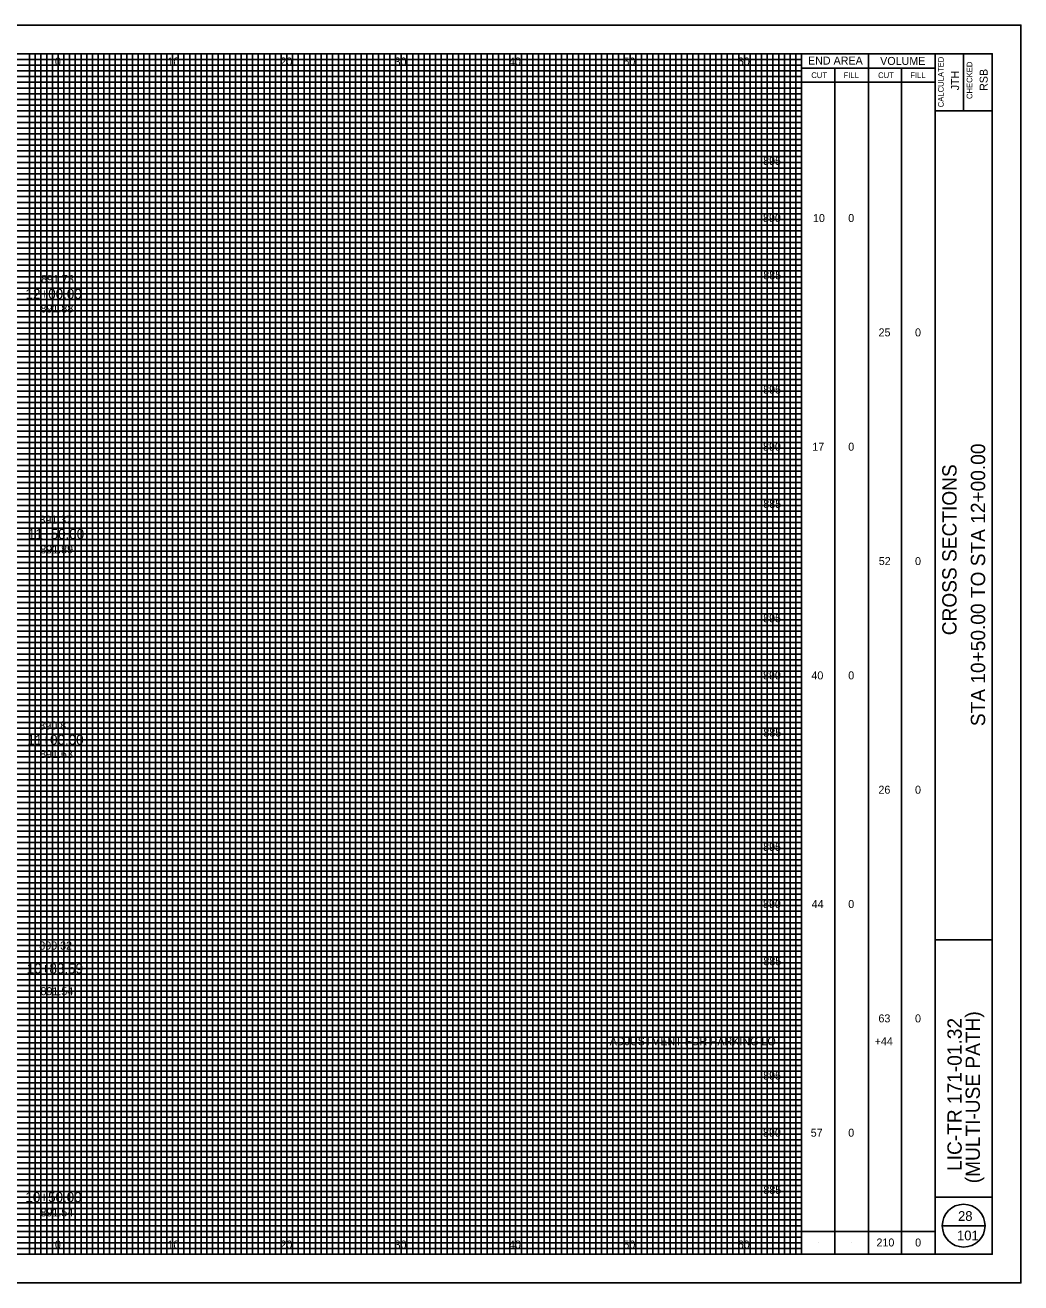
# Model space of a CAD drawing. Extents: x -10 to 160, y -2 to 2522.
# Drawn here: x 72.9 to 160, y -2.5 to 107.5 of the extents above; entities that cross this region are included whole.
import ezdxf

# ---------------------------------------------------------------- set-up
doc = ezdxf.new("R2010")
doc.units = 0
for name, color, linetype in [('GK_Cells', 7, 'Continuous'), ('GK_Patterns', 7, 'Continuous'), ('TX_P_10', 7, 'Continuous'), ('TX_X_10', 7, 'Continuous'), ('XS_P_Finished_Grade_Seeded', 7, 'Continuous'), ('XS_P_Pavt_Surface', 7, 'Continuous'), ('XS_P_Subgrade', 7, 'Continuous'), ('XS_X_Ground_Line', 7, 'Continuous')]:
    doc.layers.add(name, color=color, linetype=linetype)

msp = doc.modelspace()

# ---------------------------------------------------------------- linework, layer by layer
at = {"layer": 'GK_Cells'}
msp.add_lwpolyline([(-10, -2.5), (160, -2.5), (160, 107.5), (-10, 107.5)], close=True, dxfattribs=at)
at = {"layer": 'TX_P_10'}
for p, q in [((140.83, 0), (140.83, 105)), ((146.67, 0), (146.67, 105)), ((140.83, 103.75), (152.5, 103.75)), ((143.75, 0), (143.75, 103.75)), ((149.58, 0), (149.58, 103.75)), ((140.83, 102.5), (152.5, 102.5)), ((153.12, 2.5), (156.88, 2.5)), ((140.83, 2), (152.5, 2)), ((142.29, 1), (142.29, 1)), ((145.21, 1), (145.21, 1)), ((148.12, 1), (148.12, 1)), ((151.04, 1), (151.04, 1))]:
    msp.add_line(p, q, dxfattribs=at)
msp.add_circle((155, 2.5), 1.87, dxfattribs=at)
at = {"layer": 'TX_X_10'}
for p, q in [((75.83, 0), (75.83, 105)), ((80.83, 0), (80.83, 105)), ((85.83, 0), (85.83, 105)), ((90.83, 0), (90.83, 105)), ((95.83, 0), (95.83, 105)), ((100.83, 0), (100.83, 105)), ((105.83, 0), (105.83, 105)), ((110.83, 0), (110.83, 105)), ((115.83, 0), (115.83, 105)), ((120.83, 0), (120.83, 105)), ((125.83, 0), (125.83, 105)), ((130.83, 0), (130.83, 105)), ((135.83, 0), (135.83, 105)), ((5.83, 100), (140.83, 100)), ((5.83, 95), (140.83, 95)), ((5.83, 90), (140.83, 90)), ((5.83, 85), (140.83, 85)), ((5.83, 80), (140.83, 80)), ((5.83, 75), (140.83, 75)), ((5.83, 70), (140.83, 70)), ((5.83, 65), (140.83, 65)), ((5.83, 60), (140.83, 60)), ((5.83, 55), (140.83, 55)), ((5.83, 50), (140.83, 50)), ((5.83, 45), (140.83, 45)), ((5.83, 40), (140.83, 40)), ((5.83, 35), (140.83, 35)), ((5.83, 30), (140.83, 30)), ((5.83, 25), (140.83, 25)), ((5.83, 20), (140.83, 20)), ((5.83, 15), (140.83, 15)), ((5.83, 10), (140.83, 10)), ((5.83, 5), (140.83, 5))]:
    msp.add_line(p, q, dxfattribs=at)
at = {"layer": 'XS_P_Pavt_Surface'}
for p, q in [((152.5, 0), (152.5, 105)), ((155, 105), (155, 100)), ((152.5, 100), (157.5, 100)), ((152.5, 27.5), (157.5, 27.5)), ((152.5, 5), (157.5, 5))]:
    msp.add_line(p, q, dxfattribs=at)
msp.add_lwpolyline([(0, 105), (157.5, 105), (157.5, 0), (0, 0)], close=True, dxfattribs=at)
at = {"layer": 'XS_X_Ground_Line'}
for p, q in [((73.33, 0), (73.33, 105)), ((73.83, 0), (73.83, 105)), ((74.33, 0), (74.33, 105)), ((74.83, 0), (74.83, 105)), ((75.33, 0), (75.33, 105)), ((76.33, 0), (76.33, 105)), ((76.83, 0), (76.83, 105)), ((77.33, 0), (77.33, 105)), ((77.83, 0), (77.83, 105)), ((78.33, 0), (78.33, 105)), ((78.83, 0), (78.83, 105)), ((79.33, 0), (79.33, 105)), ((79.83, 0), (79.83, 105)), ((80.33, 0), (80.33, 105)), ((81.33, 0), (81.33, 105)), ((81.83, 0), (81.83, 105)), ((82.33, 0), (82.33, 105)), ((82.83, 0), (82.83, 105)), ((83.33, 0), (83.33, 105)), ((83.83, 0), (83.83, 105)), ((84.33, 0), (84.33, 105)), ((84.83, 0), (84.83, 105)), ((85.33, 0), (85.33, 105)), ((86.33, 0), (86.33, 105)), ((86.83, 0), (86.83, 105)), ((87.33, 0), (87.33, 105)), ((87.83, 0), (87.83, 105)), ((88.33, 0), (88.33, 105)), ((88.83, 0), (88.83, 105)), ((89.33, 0), (89.33, 105)), ((89.83, 0), (89.83, 105)), ((90.33, 0), (90.33, 105)), ((91.33, 0), (91.33, 105)), ((91.83, 0), (91.83, 105)), ((92.33, 0), (92.33, 105)), ((92.83, 0), (92.83, 105)), ((93.33, 0), (93.33, 105)), ((93.83, 0), (93.83, 105)), ((94.33, 0), (94.33, 105)), ((94.83, 0), (94.83, 105)), ((95.33, 0), (95.33, 105)), ((96.33, 0), (96.33, 105)), ((96.83, 0), (96.83, 105)), ((97.33, 0), (97.33, 105)), ((97.83, 0), (97.83, 105)), ((98.33, 0), (98.33, 105)), ((98.83, 0), (98.83, 105)), ((99.33, 0), (99.33, 105)), ((99.83, 0), (99.83, 105)), ((100.33, 0), (100.33, 105)), ((101.33, 0), (101.33, 105)), ((101.83, 0), (101.83, 105)), ((102.33, 0), (102.33, 105)), ((102.83, 0), (102.83, 105)), ((103.33, 0), (103.33, 105)), ((103.83, 0), (103.83, 105)), ((104.33, 0), (104.33, 105)), ((104.83, 0), (104.83, 105)), ((105.33, 0), (105.33, 105)), ((106.33, 0), (106.33, 105)), ((106.83, 0), (106.83, 105)), ((107.33, 0), (107.33, 105)), ((107.83, 0), (107.83, 105)), ((108.33, 0), (108.33, 105)), ((108.83, 0), (108.83, 105)), ((109.33, 0), (109.33, 105)), ((109.83, 0), (109.83, 105)), ((110.33, 0), (110.33, 105)), ((111.33, 0), (111.33, 105)), ((111.83, 0), (111.83, 105)), ((112.33, 0), (112.33, 105)), ((112.83, 0), (112.83, 105)), ((113.33, 0), (113.33, 105)), ((113.83, 0), (113.83, 105)), ((114.33, 0), (114.33, 105)), ((114.83, 0), (114.83, 105)), ((115.33, 0), (115.33, 105)), ((116.33, 0), (116.33, 105)), ((116.83, 0), (116.83, 105)), ((117.33, 0), (117.33, 105)), ((117.83, 0), (117.83, 105)), ((118.33, 0), (118.33, 105)), ((118.83, 0), (118.83, 105)), ((119.33, 0), (119.33, 105)), ((119.83, 0), (119.83, 105)), ((120.33, 0), (120.33, 105)), ((121.33, 0), (121.33, 105)), ((121.83, 0), (121.83, 105)), ((122.33, 0), (122.33, 105)), ((122.83, 0), (122.83, 105)), ((123.33, 0), (123.33, 105)), ((123.83, 0), (123.83, 105)), ((124.33, 0), (124.33, 105)), ((124.83, 0), (124.83, 105)), ((125.33, 0), (125.33, 105)), ((126.33, 0), (126.33, 105)), ((126.83, 0), (126.83, 105)), ((127.33, 0), (127.33, 105)), ((127.83, 0), (127.83, 105)), ((128.33, 0), (128.33, 105)), ((128.83, 0), (128.83, 105)), ((129.33, 0), (129.33, 105)), ((129.83, 0), (129.83, 105)), ((130.33, 0), (130.33, 105)), ((131.33, 0), (131.33, 105)), ((131.83, 0), (131.83, 105)), ((132.33, 0), (132.33, 105)), ((132.83, 0), (132.83, 105)), ((133.33, 0), (133.33, 105)), ((133.83, 0), (133.83, 105)), ((134.33, 0), (134.33, 105)), ((134.83, 0), (134.83, 105)), ((135.33, 0), (135.33, 105)), ((136.33, 0), (136.33, 105)), ((136.83, 0), (136.83, 105)), ((137.33, 0), (137.33, 105)), ((137.83, 0), (137.83, 105)), ((138.33, 0), (138.33, 105)), ((138.83, 0), (138.83, 105)), ((139.33, 0), (139.33, 105)), ((139.83, 0), (139.83, 105)), ((140.33, 0), (140.33, 105)), ((5.83, 104.5), (140.83, 104.5)), ((5.83, 104), (140.83, 104)), ((5.83, 103.5), (140.83, 103.5)), ((5.83, 103), (140.83, 103)), ((5.83, 102.5), (140.83, 102.5)), ((5.83, 102), (140.83, 102)), ((5.83, 101.5), (140.83, 101.5)), ((5.83, 101), (140.83, 101)), ((5.83, 100.5), (140.83, 100.5)), ((5.83, 99.5), (140.83, 99.5)), ((5.83, 99), (140.83, 99)), ((5.83, 98.5), (140.83, 98.5)), ((5.83, 98), (140.83, 98)), ((5.83, 97.5), (140.83, 97.5)), ((5.83, 97), (140.83, 97)), ((5.83, 96.5), (140.83, 96.5)), ((5.83, 96), (140.83, 96)), ((5.83, 95.5), (140.83, 95.5)), ((5.83, 94.5), (140.83, 94.5)), ((5.83, 94), (140.83, 94)), ((5.83, 93.5), (140.83, 93.5)), ((5.83, 93), (140.83, 93)), ((5.83, 92.5), (140.83, 92.5)), ((5.83, 92), (140.83, 92)), ((5.83, 91.5), (140.83, 91.5)), ((5.83, 91), (140.83, 91)), ((5.83, 90.5), (140.83, 90.5)), ((5.83, 89.5), (140.83, 89.5)), ((5.83, 89), (140.83, 89)), ((5.83, 88.5), (140.83, 88.5)), ((5.83, 88), (140.83, 88)), ((5.83, 87.5), (140.83, 87.5)), ((5.83, 87), (140.83, 87)), ((5.83, 86.5), (140.83, 86.5)), ((5.83, 86), (140.83, 86)), ((5.83, 85.5), (140.83, 85.5)), ((5.83, 84.5), (140.83, 84.5)), ((5.83, 84), (140.83, 84)), ((5.83, 83.5), (140.83, 83.5)), ((5.83, 83), (140.83, 83)), ((5.83, 82.5), (140.83, 82.5)), ((5.83, 82), (140.83, 82)), ((5.83, 81.5), (140.83, 81.5)), ((5.83, 81), (140.83, 81)), ((5.83, 80.5), (140.83, 80.5)), ((5.83, 79.5), (140.83, 79.5)), ((5.83, 79), (140.83, 79)), ((5.83, 78.5), (140.83, 78.5)), ((5.83, 78), (140.83, 78)), ((5.83, 77.5), (140.83, 77.5)), ((5.83, 77), (140.83, 77)), ((5.83, 76.5), (140.83, 76.5)), ((5.83, 76), (140.83, 76)), ((5.83, 75.5), (140.83, 75.5)), ((5.83, 74.5), (140.83, 74.5)), ((5.83, 74), (140.83, 74)), ((5.83, 73.5), (140.83, 73.5)), ((5.83, 73), (140.83, 73)), ((5.83, 72.5), (140.83, 72.5)), ((5.83, 72), (140.83, 72)), ((5.83, 71.5), (140.83, 71.5)), ((5.83, 71), (140.83, 71)), ((5.83, 70.5), (140.83, 70.5)), ((5.83, 69.5), (140.83, 69.5)), ((5.83, 69), (140.83, 69)), ((5.83, 68.5), (140.83, 68.5)), ((5.83, 68), (140.83, 68)), ((5.83, 67.5), (140.83, 67.5)), ((5.83, 67), (140.83, 67)), ((5.83, 66.5), (140.83, 66.5)), ((5.83, 66), (140.83, 66)), ((5.83, 65.5), (140.83, 65.5)), ((5.83, 64.5), (140.83, 64.5)), ((5.83, 64), (140.83, 64)), ((5.83, 63.5), (140.83, 63.5)), ((5.83, 63), (140.83, 63)), ((5.83, 62.5), (140.83, 62.5)), ((5.83, 62), (140.83, 62)), ((5.83, 61.5), (140.83, 61.5)), ((5.83, 61), (140.83, 61)), ((5.83, 60.5), (140.83, 60.5)), ((5.83, 59.5), (140.83, 59.5)), ((5.83, 59), (140.83, 59)), ((5.83, 58.5), (140.83, 58.5)), ((5.83, 58), (140.83, 58)), ((5.83, 57.5), (140.83, 57.5)), ((5.83, 57), (140.83, 57)), ((5.83, 56.5), (140.83, 56.5)), ((5.83, 56), (140.83, 56)), ((5.83, 55.5), (140.83, 55.5)), ((5.83, 54.5), (140.83, 54.5)), ((5.83, 54), (140.83, 54)), ((5.83, 53.5), (140.83, 53.5)), ((5.83, 53), (140.83, 53)), ((5.83, 52.5), (140.83, 52.5)), ((5.83, 52), (140.83, 52)), ((5.83, 51.5), (140.83, 51.5)), ((5.83, 51), (140.83, 51)), ((5.83, 50.5), (140.83, 50.5)), ((5.83, 49.5), (140.83, 49.5)), ((5.83, 49), (140.83, 49)), ((5.83, 48.5), (140.83, 48.5)), ((5.83, 48), (140.83, 48)), ((5.83, 47.5), (140.83, 47.5)), ((5.83, 47), (140.83, 47)), ((5.83, 46.5), (140.83, 46.5)), ((5.83, 46), (140.83, 46)), ((5.83, 45.5), (140.83, 45.5)), ((5.83, 44.5), (140.83, 44.5)), ((5.83, 44), (140.83, 44)), ((5.83, 43.5), (140.83, 43.5)), ((5.83, 43), (140.83, 43)), ((5.83, 42.5), (140.83, 42.5)), ((5.83, 42), (140.83, 42)), ((5.83, 41.5), (140.83, 41.5)), ((5.83, 41), (140.83, 41)), ((5.83, 40.5), (140.83, 40.5)), ((5.83, 39.5), (140.83, 39.5)), ((5.83, 39), (140.83, 39)), ((5.83, 38.5), (140.83, 38.5)), ((5.83, 38), (140.83, 38)), ((5.83, 37.5), (140.83, 37.5)), ((5.83, 37), (140.83, 37)), ((5.83, 36.5), (140.83, 36.5)), ((5.83, 36), (140.83, 36)), ((5.83, 35.5), (140.83, 35.5)), ((5.83, 34.5), (140.83, 34.5)), ((5.83, 34), (140.83, 34)), ((5.83, 33.5), (140.83, 33.5)), ((5.83, 33), (140.83, 33)), ((5.83, 32.5), (140.83, 32.5)), ((5.83, 32), (140.83, 32)), ((5.83, 31.5), (140.83, 31.5)), ((5.83, 31), (140.83, 31)), ((5.83, 30.5), (140.83, 30.5)), ((5.83, 29.5), (140.83, 29.5)), ((5.83, 29), (140.83, 29)), ((5.83, 28.5), (140.83, 28.5)), ((5.83, 28), (140.83, 28)), ((5.83, 27.5), (140.83, 27.5)), ((5.83, 27), (140.83, 27)), ((5.83, 26.5), (140.83, 26.5)), ((5.83, 26), (140.83, 26)), ((5.83, 25.5), (140.83, 25.5)), ((5.83, 24.5), (140.83, 24.5)), ((5.83, 24), (140.83, 24)), ((5.83, 23.5), (140.83, 23.5)), ((5.83, 23), (140.83, 23)), ((5.83, 22.5), (140.83, 22.5)), ((5.83, 22), (140.83, 22)), ((5.83, 21.5), (140.83, 21.5)), ((5.83, 21), (140.83, 21)), ((5.83, 20.5), (140.83, 20.5)), ((5.83, 19.5), (140.83, 19.5)), ((5.83, 19), (140.83, 19)), ((5.83, 18.5), (140.83, 18.5)), ((5.83, 18), (140.83, 18)), ((5.83, 17.5), (140.83, 17.5)), ((5.83, 17), (140.83, 17)), ((5.83, 16.5), (140.83, 16.5)), ((5.83, 16), (140.83, 16)), ((5.83, 15.5), (140.83, 15.5)), ((5.83, 14.5), (140.83, 14.5)), ((5.83, 14), (140.83, 14)), ((5.83, 13.5), (140.83, 13.5)), ((5.83, 13), (140.83, 13)), ((5.83, 12.5), (140.83, 12.5)), ((5.83, 12), (140.83, 12)), ((5.83, 11.5), (140.83, 11.5)), ((5.83, 11), (140.83, 11)), ((5.83, 10.5), (140.83, 10.5)), ((5.83, 9.5), (140.83, 9.5)), ((5.83, 9), (140.83, 9)), ((5.83, 8.5), (140.83, 8.5)), ((5.83, 8), (140.83, 8)), ((5.83, 7.5), (140.83, 7.5)), ((5.83, 7), (140.83, 7)), ((5.83, 6.5), (140.83, 6.5)), ((5.83, 6), (140.83, 6)), ((5.83, 5.5), (140.83, 5.5)), ((5.83, 4.5), (140.83, 4.5)), ((5.83, 4), (140.83, 4)), ((5.83, 3.5), (140.83, 3.5)), ((5.83, 3), (140.83, 3)), ((5.83, 2.5), (140.83, 2.5)), ((5.83, 2), (140.83, 2)), ((5.83, 1.5), (140.83, 1.5)), ((5.83, 1), (140.83, 1)), ((5.83, 0.5), (140.83, 0.5))]:
    msp.add_line(p, q, dxfattribs=at)

# ---------------------------------------------------------------- texts
at = {"layer": 'GK_Patterns'}
for s, height, p in [('0', 0.7, (75.55, 103.97)), ('0', 0.7, (75.55, 103.97)), ('10', 0.7, (85.39, 103.97)), ('20', 0.7, (95.26, 103.97)), ('30', 0.7, (105.25, 103.97)), ('40', 0.7, (115.25, 103.97)), ('50', 0.7, (125.25, 103.97)), ('60', 0.7, (135.25, 103.97)), ('895', 0.7, (137.47, 95.28)), ('890', 0.7, (137.46, 90.28)), ('10', 0.7, (141.83, 90.28)), ('0', 0.7, (144.91, 90.28)), ('885', 0.7, (137.48, 85.28)), ('12+00.00', 0.875, (72.98, 83.56)), ('25', 0.7, (147.56, 80.28)), ('0', 0.7, (150.75, 80.28)), ('895', 0.7, (137.47, 75.28)), ('890', 0.7, (137.46, 70.28)), ('17', 0.7, (141.77, 70.28)), ('0', 0.7, (144.91, 70.28)), ('885', 0.7, (137.48, 65.28)), ('11+50.00', 0.875, (73.19, 62.56)), ('52', 0.7, (147.58, 60.28)), ('0', 0.7, (150.75, 60.28)), ('895', 0.7, (137.47, 55.28)), ('890', 0.7, (137.46, 50.28)), ('40', 0.7, (141.69, 50.28)), ('0', 0.7, (144.91, 50.28)), ('11+00.00', 0.875, (73.14, 44.56)), ('885', 0.7, (137.49, 45.28)), ('26', 0.7, (147.55, 40.28)), ('0', 0.7, (150.75, 40.28)), ('895', 0.7, (137.47, 35.28)), ('890', 0.7, (137.46, 30.28)), ('44', 0.7, (141.71, 30.28)), ('0', 0.7, (144.91, 30.28)), ('10+83.59', 0.875, (73.09, 24.56)), ('885', 0.7, (137.49, 25.28)), ('63', 0.7, (147.55, 20.28)), ('0', 0.7, (150.75, 20.28)), ('ADJUSTMENT FOR PARKING LOT', 0.7, (124.06, 18.28)), ('+44', 0.7, (147.22, 18.28)), ('895', 0.7, (137.47, 15.28)), ('890', 0.7, (137.46, 10.28)), ('57', 0.7, (141.63, 10.28)), ('0', 0.7, (144.91, 10.28)), ('885', 0.7, (137.49, 5.28)), ('10+50.00', 0.875, (72.97, 4.56)), ('0', 0.7, (75.55, 0.5)), ('0', 0.7, (75.55, 0.5)), ('10', 0.7, (85.39, 0.5)), ('20', 0.7, (95.26, 0.5)), ('30', 0.7, (105.25, 0.5)), ('40', 0.7, (115.25, 0.5)), ('50', 0.7, (125.25, 0.5)), ('60', 0.7, (135.25, 0.5)), ('210', 0.7, (147.38, 0.68)), ('0', 0.7, (150.76, 0.68))]:
    msp.add_text(s, height=height, dxfattribs=at).set_placement(p)
at = {"layer": 'TX_P_10'}
for s, height, p in [('END AREA', 0.7, (141.39, 104.05)), ('VOLUME', 0.7, (147.7, 104.02)), ('CUT', 0.5, (141.68, 102.87)), ('FILL', 0.5, (144.5, 102.87)), ('CUT', 0.5, (147.52, 102.87)), ('FILL', 0.5, (150.34, 102.87)), ('28', 0.85, (154.51, 2.92)), ('101', 0.85, (154.42, 1.22))]:
    msp.add_text(s, height=height, dxfattribs=at).set_placement(p)
for s, height, p in [('CALCULATED', 0.5, (153.26, 100.32)), ('JTH', 0.7, (154.6, 101.8)), ('CHECKED', 0.5, (155.76, 101.04)), ('RSB', 0.7, (157.1, 101.75)), ('STA 10+50.00 TO STA 12+00.00', 1.25, (156.88, 46.19)), ('CROSS SECTIONS', 1.25, (154.38, 54.14)), ('(MULTI-USE PATH)', 1.25, (156.42, 6.21)), ('LIC-TR 171-01.32', 1.25, (154.83, 7.29))]:
    msp.add_text(s, height=height, rotation=90, dxfattribs=at).set_placement(p)
at = {"layer": 'XS_P_Finished_Grade_Seeded'}
for s, p in [('891.88', (74.29, 82.37)), ('891.89', (74.27, 61.3)), ('891.63', (74.25, 43.4)), ('891.54', (74.29, 22.66)), ('891.54', (74.29, 3.31))]:
    msp.add_text(s, height=0.7, dxfattribs=at).set_placement(p)
at = {"layer": 'XS_P_Subgrade'}
for s, p in [('891.73', (74.34, 84.95)), ('891.37', (74.19, 63.9)), ('890.81', (74.18, 45.9)), ('890.32', (74.18, 26.65))]:
    msp.add_text(s, height=0.7, dxfattribs=at).set_placement(p)

doc.saveas('drawing.dxf')
